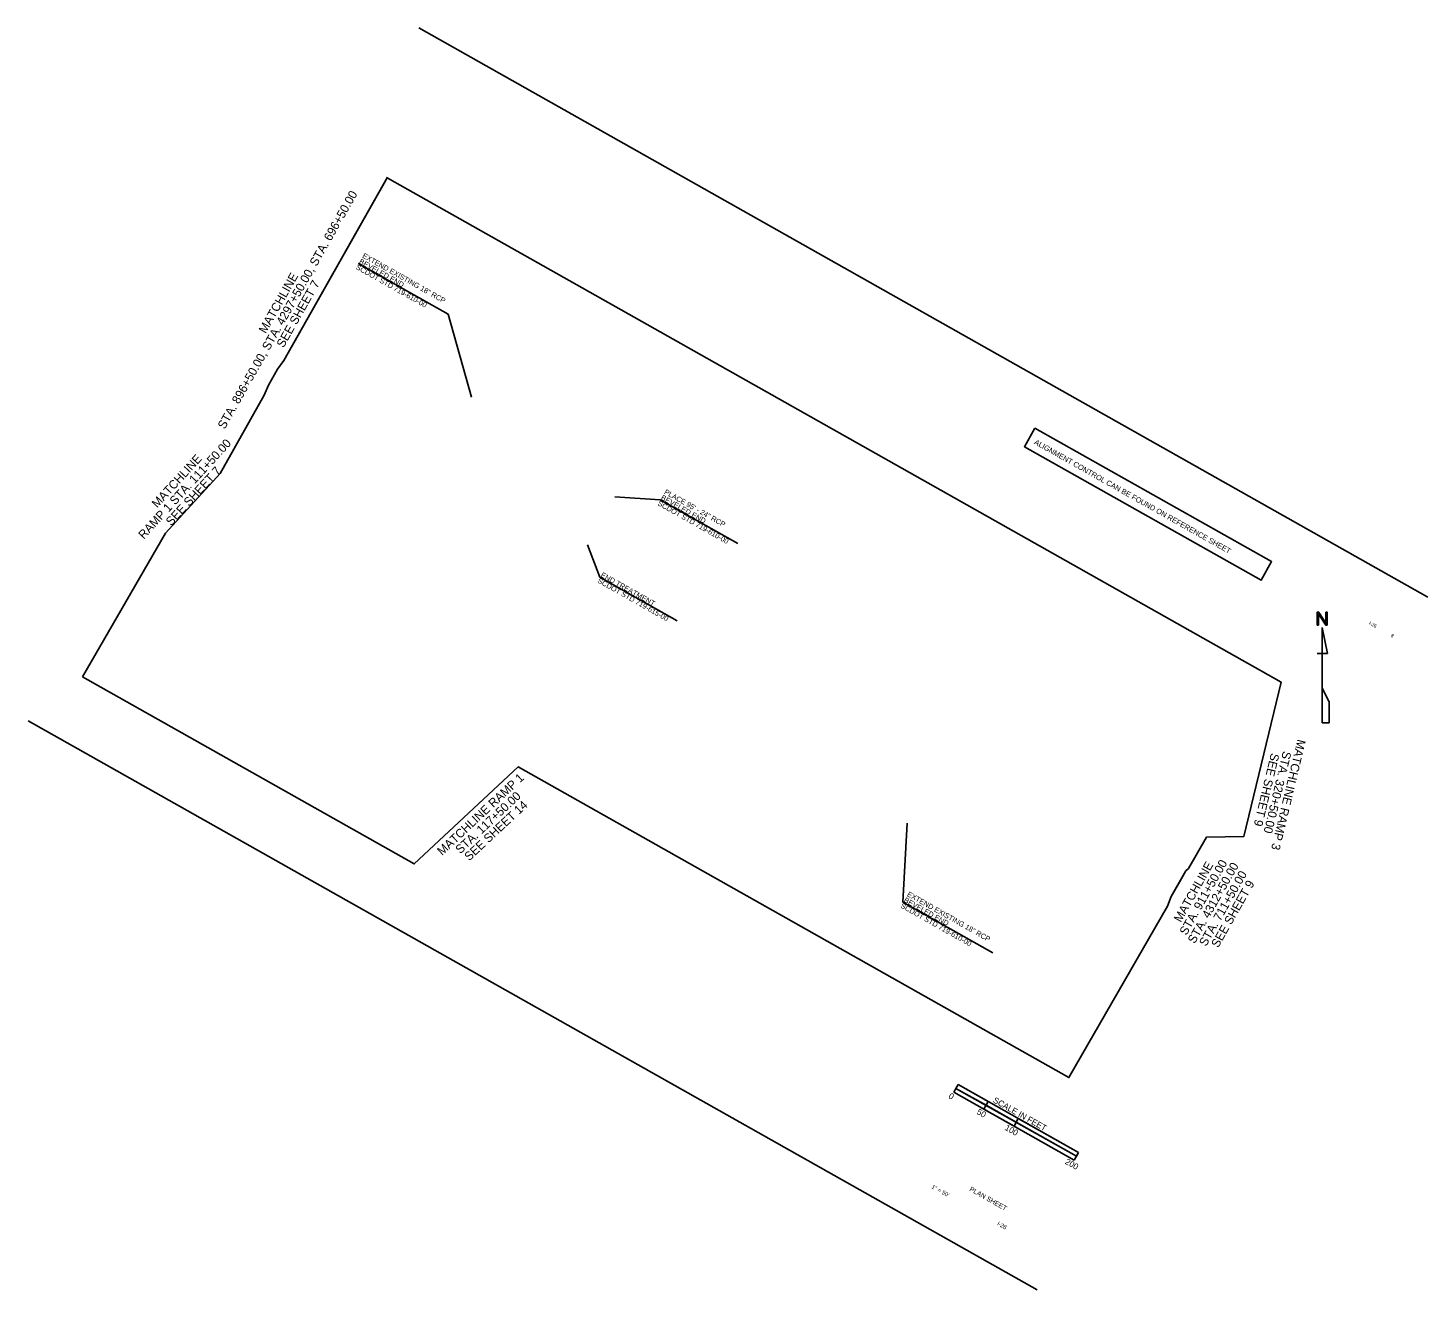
# Model space of a CAD drawing. Extents: x 2219160 to 2221184, y 469008 to 470833.
import ezdxf

# ---------------------------------------------------------------- set-up
doc = ezdxf.new("R2010")
doc.units = 0
for name, color, linetype in [('North Arrow', 7, 'Continuous'), ('RD_HY_Misc', 7, 'Continuous'), ('RD_SHT_MatchLine', 7, 'Continuous'), ('RD_SHT_ShtClip', 7, 'Continuous'), ('RD_SHT_TX', 7, 'Continuous')]:
    doc.layers.add(name, color=color, linetype=linetype)

msp = doc.modelspace()

# ---------------------------------------------------------------- linework, layer by layer
at = {"layer": 'North Arrow'}
for p, q in [((2221030.7, 469965.6), (2221030.7, 469928.1)), ((2221038.2, 469928.1), (2221030.7, 469965.6)), ((2221030.7, 469928.1), (2221023.2, 469928.1)), ((2221030.7, 469928.1), (2221030.7, 469878.1)), ((2221030.7, 469928.1), (2221038.2, 469928.1)), ((2221030.7, 469878.1), (2221030.7, 469828.1))]:
    msp.add_line(p, q, dxfattribs=at)
for points in [[(2221023.5, 469972), (2221023.5, 469969.3), (2221025.2, 469969.3), (2221025.2, 469972), (2221025.2, 469985.5), (2221027.2, 469985.5), (2221025.5, 469988.1), (2221023.5, 469988.1), (2221023.5, 469985.5)], [(2221034.1, 469972), (2221035.9, 469969.3), (2221037.8, 469969.3), (2221037.8, 469972), (2221036.1, 469972), (2221027.2, 469985.5), (2221025.2, 469985.5)], [(2221036.1, 469988.1), (2221036.1, 469972), (2221037.8, 469972), (2221037.8, 469988.1)]]:
    msp.add_lwpolyline(points, close=True, dxfattribs=at)
msp.add_lwpolyline([(2221030.7, 469828.1), (2221040.7, 469828.1), (2221040.7, 469858.1), (2221030.7, 469878.1)], dxfattribs=at)
at = {"layer": 'RD_HY_Misc'}
for p, q in [((2219767.1, 470418.6), (2219637, 470492)), ((2220185.9, 470087.1), (2220073.4, 470150.5)), ((2220098.4, 469975.6), (2219986.4, 470038.7)), ((2220554.6, 469495.4), (2220424.6, 469568.7))]:
    msp.add_line(p, q, dxfattribs=at)
for points in [[(2219767.1, 470418.6), (2219800.9, 470298.7)], [(2220073.4, 470150.5), (2220008, 470154.7)], [(2219986.4, 470038.7), (2219968.5, 470085.1)], [(2220424.6, 469568.7), (2220430.6, 469682.7)]]:
    msp.add_lwpolyline(points, dxfattribs=at)
at = {"layer": 'RD_SHT_MatchLine'}
for p, q in [((2219529.7, 470352), (2219679.2, 470617.1)), ((2219678.7, 470616.1), (2219678.7, 470616.1)), ((2219507.6, 470316.4), (2219520.4, 470339.1)), ((2219520.4, 470339.1), (2219529.7, 470352)), ((2219437.3, 470188.3), (2219501.3, 470301.7)), ((2219501.3, 470301.7), (2219507.6, 470316.4)), ((2219437.3, 470188.3), (2219358.4, 470102.4)), ((2219358.4, 470102.4), (2219238.7, 469894.6)), ((2220971.1, 469887), (2220917.6, 469663.8)), ((2219718.1, 469624.1), (2219868.1, 469764.3)), ((2220837.4, 469617.6), (2220863.4, 469662.8)), ((2220863.4, 469662.8), (2220917.6, 469663.8)), ((2220812.4, 469576.7), (2220833.7, 469613.8)), ((2220833.7, 469613.8), (2220837.4, 469617.6)), ((2220807.1, 469563.1), (2220812.4, 469576.7)), ((2220807.1, 469563.1), (2220664.6, 469315))]:
    msp.add_line(p, q, dxfattribs=at)
at = {"layer": 'RD_SHT_ShtClip'}
msp.add_lwpolyline([(2219238.7, 469894.6), (2219358.4, 470102.4), (2219437.3, 470188.3), (2219501.3, 470301.7), (2219507.6, 470316.4), (2219520.4, 470339.1), (2219529.7, 470352), (2219678.7, 470616.1), (2220971.1, 469887), (2220917.6, 469663.8), (2220863.4, 469662.8), (2220837.4, 469617.6), (2220833.7, 469613.8), (2220823, 469595.2), (2220812.4, 469576.7), (2220807.1, 469563.1), (2220664.6, 469315), (2219868.1, 469764.3), (2219718.1, 469624.1)], close=True, dxfattribs=at)
at = {"layer": 'RD_SHT_TX'}
for p, q in [((2221183.6, 470009.6), (2219724.7, 470832.6)), ((2219159.7, 469830.9), (2220618.6, 469008)), ((2220504.2, 469305), (2220498.1, 469294.1)), ((2220504.2, 469305), (2220501.1, 469299.5)), ((2220504.2, 469305), (2220678.4, 469206.7)), ((2220547.7, 469280.4), (2220504.2, 469305)), ((2220498.1, 469294.1), (2220672.3, 469195.8)), ((2220501.1, 469299.5), (2220675.3, 469201.3)), ((2220501.1, 469299.5), (2220544.7, 469275)), ((2220547.7, 469280.4), (2220541.6, 469269.5)), ((2220544.7, 469275), (2220541.6, 469269.5)), ((2220541.6, 469269.5), (2220585.2, 469244.9)), ((2220544.7, 469275), (2220547.7, 469280.4)), ((2220588.2, 469250.4), (2220544.7, 469275)), ((2220591.3, 469255.8), (2220585.2, 469244.9)), ((2220585.2, 469244.9), (2220588.2, 469250.4)), ((2220591.3, 469255.8), (2220588.2, 469250.4)), ((2220588.2, 469250.4), (2220675.3, 469201.3)), ((2220678.4, 469206.7), (2220591.3, 469255.8)), ((2220678.4, 469206.7), (2220672.3, 469195.8)), ((2220675.3, 469201.3), (2220678.4, 469206.7))]:
    msp.add_line(p, q, dxfattribs=at)
msp.add_lwpolyline([(2220615.4, 470254.1), (2220957.6, 470061.1), (2220942.3, 470034), (2220600.2, 470227.1)], close=True, dxfattribs=at)

# ---------------------------------------------------------------- texts
at = {"layer": 'RD_HY_Misc'}
for s, p in [('BEVELED END', (2219637.5, 470492.8)), ('EXTEND EXISTING 18" RCP', (2219642.2, 470501.1)), ('SCDOT STD 719-610-00', (2219632.9, 470484.6)), ('BEVELED END', (2220073.9, 470151.4)), ('PLACE 95\' - 24" RCP', (2220078.6, 470159.6)), ('SCDOT STD 719-610-00', (2220069.2, 470143.1)), ('SCDOT STD 719-615-00', (2219982.3, 470031.3)), ('END TREATMENT', (2219986.9, 470039.6)), ('BEVELED END', (2220425.1, 469569.6)), ('EXTEND EXISTING 18" RCP', (2220429.7, 469577.9)), ('SCDOT STD 719-610-00', (2220420.4, 469561.3))]:
    msp.add_text(s, height=7.5, rotation=330.5715, dxfattribs=at).set_placement(p)
at = {"layer": 'RD_SHT_MatchLine'}
for s, rotation, p in [('STA. 896+50.00, STA. 4297+50.00, STA. 696+50.00', 60.5715, (2219444, 470251.6)), ('MATCHLINE', 60.5715, (2219503.3, 470390)), ('SEE SHEET 7', 60.5715, (2219529.1, 470369.4)), ('RAMP 1 STA. 111+50.00', 47.3934, (2219327.1, 470092.8)), ('MATCHLINE ', 47.3934, (2219346.5, 470137.9)), ('SEE SHEET 7', 47.3934, (2219366.8, 470112)), ('MATCHLINE RAMP 3', 256.5039, (2220994.9, 469804.8)), ('SEE SHEET 9', 256.5039, (2220956.7, 469784.9)), ('STA. 320+50.00', 256.5039, (2220974.1, 469787.8)), ('MATCHLINE RAMP 1', 43.0789, (2219758.4, 469635.5)), ('STA. 117+50.00', 43.0789, (2219784.7, 469637.8)), ('SEE SHEET 14', 43.0789, (2219797.6, 469627.6)), ('STA. 911+50.00', 60.5715, (2220834.4, 469519.9)), ('MATCHLINE', 60.5715, (2220826.3, 469538.6)), ('STA. 4312+50.00', 60.5715, (2220846.3, 469507.8)), ('STA. 711+50.00', 60.5715, (2220862.8, 469503.9)), ('SEE SHEET 9', 60.5715, (2220880.3, 469501.9))]:
    msp.add_text(s, height=12.5, rotation=rotation, dxfattribs=at).set_placement(p)
at = {"layer": 'RD_SHT_TX'}
for s, height, p in [('ALIGNMENT CONTROL CAN BE FOUND ON REFERENCE SHEET', 7.656, (2220613.5, 470231.5)), ('I-26', 5, (2221097.5, 469970.6)), ('8', 5, (2221129.2, 469952.7)), ('0', 8.75, (2220489.6, 469285.9)), ('SCALE IN FEET', 8.75, (2220553.9, 469279.8)), ('50', 8.75, (2220530.3, 469263)), ('100', 8.75, (2220571, 469240)), ('200', 8.75, (2220658.1, 469190.9)), ('1" = 50\'', 6, (2220465.2, 469155.6)), ('PLAN SHEET', 7, (2220520, 469151.7)), ('I-26', 6, (2220560.1, 469102.1))]:
    msp.add_text(s, height=height, rotation=330.5715, dxfattribs=at).set_placement(p)

doc.saveas('drawing.dxf')
